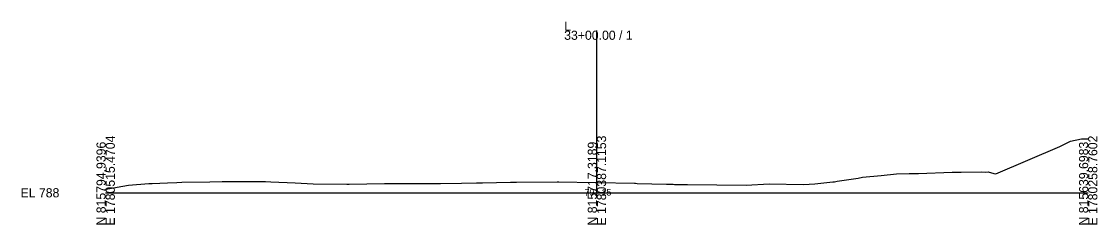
# Model space of a CAD drawing. Extents: x -26 to 7903, y -10 to 9573.
# Drawn here: x -25.7 to 302.8, y 3990.3 to 4052.4 of the extents above; entities that cross this region are included whole.
import ezdxf

# ---------------------------------------------------------------- set-up
doc = ezdxf.new("R2010")
doc.units = 0
for name, color, linetype in [('Exist Cross Section Cell', 7, 'Continuous'), ('Exist XS Center Line Elevation Label', 7, 'Continuous'), ('Exist XS Ground Line', 7, 'Continuous')]:
    doc.layers.add(name, color=color, linetype=linetype)

msp = doc.modelspace()

# ---------------------------------------------------------------- linework, layer by layer
at = {"layer": 'Exist Cross Section Cell'}
for p, q in [((150, 4000), (150, 4049.56)), ((0, 4000), (150, 4000)), ((150, 4000), (300, 4000))]:
    msp.add_line(p, q, dxfattribs=at)
at = {"layer": 'Exist XS Ground Line'}
for p, q in [((291.99, 4014.44), (294.57, 4015.8)), ((294.57, 4015.8), (297.93, 4016.52)), ((297.93, 4016.52), (300, 4016.5)), ((271.78, 4005.8), (291.33, 4014.17)), ((291.33, 4014.17), (291.99, 4014.44)), ((231.1, 4004.75), (236.77, 4005.29)), ((236.77, 4005.29), (241.46, 4005.81)), ((241.46, 4005.81), (245.31, 4005.87)), ((245.31, 4005.87), (246.83, 4005.87)), ((246.83, 4005.87), (248.19, 4005.92)), ((248.19, 4005.92), (258.44, 4006.27)), ((258.44, 4006.27), (261.22, 4006.28)), ((261.22, 4006.28), (267.3, 4006.36)), ((267.3, 4006.36), (268.64, 4006.33)), ((268.64, 4006.33), (269.43, 4006.37)), ((269.43, 4006.37), (271.15, 4005.86)), ((271.15, 4005.86), (271.78, 4005.8)), ((0.67, 4001.23), (6.99, 4002.36)), ((6.99, 4002.36), (13.23, 4002.85)), ((13.23, 4002.85), (14.21, 4002.89)), ((14.21, 4002.89), (18.93, 4003.01)), ((18.93, 4003.01), (21.78, 4003.15)), ((21.78, 4003.15), (23.23, 4003.23)), ((23.23, 4003.23), (31.85, 4003.37)), ((31.85, 4003.37), (35.6, 4003.44)), ((35.6, 4003.44), (43.77, 4003.47)), ((43.77, 4003.47), (47.05, 4003.5)), ((47.05, 4003.5), (48.79, 4003.44)), ((48.79, 4003.44), (50.46, 4003.37)), ((50.46, 4003.37), (57.86, 4003.05)), ((57.86, 4003.05), (63.32, 4002.76)), ((63.32, 4002.76), (73.59, 4002.66)), ((73.59, 4002.66), (74.35, 4002.66)), ((74.35, 4002.66), (85.15, 4002.81)), ((85.15, 4002.81), (85.86, 4002.81)), ((85.86, 4002.81), (86.61, 4002.83)), ((86.61, 4002.83), (95.27, 4002.87)), ((95.27, 4002.87), (102.26, 4002.89)), ((102.26, 4002.89), (108.6, 4002.97)), ((108.6, 4002.97), (113.25, 4003.04)), ((113.25, 4003.04), (115.06, 4003.06)), ((115.06, 4003.06), (123.65, 4003.26)), ((123.65, 4003.26), (125.47, 4003.27)), ((125.47, 4003.27), (137.84, 4003.39)), ((137.84, 4003.39), (138.38, 4003.4)), ((138.38, 4003.4), (149.49, 4003.17)), ((149.49, 4003.17), (150, 4003.15)), ((150, 4003.15), (161.43, 4002.91)), ((161.43, 4002.91), (161.81, 4002.9)), ((161.81, 4002.9), (162.29, 4002.88)), ((162.29, 4002.88), (171.22, 4002.64)), ((171.22, 4002.64), (173.33, 4002.59)), ((173.33, 4002.59), (173.68, 4002.58)), ((173.68, 4002.58), (174.16, 4002.56)), ((174.16, 4002.56), (175.28, 4002.55)), ((175.28, 4002.55), (177.65, 4002.51)), ((177.65, 4002.51), (195.62, 4002.37)), ((195.62, 4002.37), (202.55, 4002.71)), ((202.55, 4002.71), (213.04, 4002.57)), ((213.04, 4002.57), (216.58, 4002.75)), ((216.58, 4002.75), (217.41, 4002.8)), ((217.41, 4002.8), (222.07, 4003.3)), ((222.07, 4003.3), (222.53, 4003.39)), ((222.53, 4003.39), (223.36, 4003.51)), ((223.36, 4003.51), (229.75, 4004.5)), ((229.75, 4004.5), (231.1, 4004.75)), ((0, 4001.09), (0.67, 4001.23))]:
    msp.add_line(p, q, dxfattribs=at)

# ---------------------------------------------------------------- texts
at = {"layer": 'Exist Cross Section Cell'}
for s, p in [('L', (140, 4049.56)), ('33+00.00 / 1', (140, 4046.76)), ('EL 788', (-26, 3998.6))]:
    msp.add_text(s, height=2.8, dxfattribs=at).set_placement(p)
for s, p in [('N 815794.9396', (0, 3990)), ('E 1780515.4704', (2.8, 3990)), ('N 815717.3189', (150, 3990)), ('E 1780387.1153', (152.8, 3990)), ('N 815639.6983', (300, 3990)), ('E 1780258.7602', (302.8, 3990))]:
    msp.add_text(s, height=2.8, rotation=90, dxfattribs=at).set_placement(p)
at = {"layer": 'Exist XS Center Line Elevation Label'}
msp.add_text('791.15', height=2, dxfattribs=at).set_placement((146.22, 3999.15))

doc.saveas('drawing.dxf')
